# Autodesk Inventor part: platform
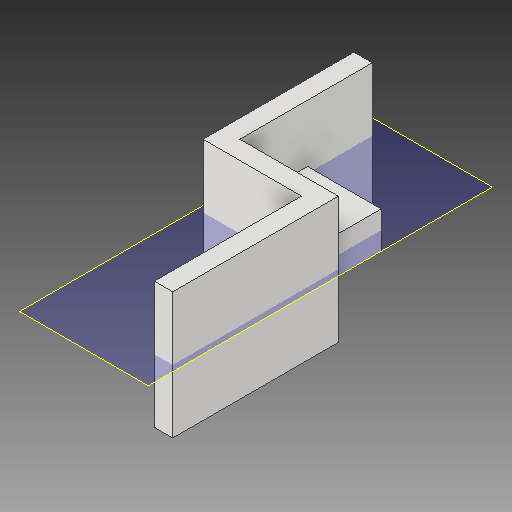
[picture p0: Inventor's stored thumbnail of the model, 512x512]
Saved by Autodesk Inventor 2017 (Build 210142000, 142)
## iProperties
Created: 2017-04
Part Number: platform
Material: LCP Plastic
Document SubType Name: Modeling
Designer: 1460374
Density: 1.626 g/cm^3
Appearance: Smooth - White
Author: 1460374
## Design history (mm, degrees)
sketch "Sketch1"
  geometry: L1 (-324.026, 5.525)-(-324.026, 11.875) reference; L2 (-332.942, 11.875)-(-324.026, 5.525) reference; L3 (-332.942, 11.875)-(-315.942, 11.875); L4 (-315.942, 11.875)-(-315.942, -9.969); L5 (-315.942, -9.969)-(-332.942, -9.969); L6 (-332.942, -9.969)-(-332.942, 11.875); 1 further point
  constraints: 8 end point, 2 parallel, 1 horizontal, 1 perpendicular
  dimensions: "d0" = 17 distance of L4.end L5.end; "d1" = 21.844 distance of L3.end L4.end
extrude "Extrusion1" new body sketch "Sketch1" distance "d2" = 3.175; taper "d3" = 0 deg
sketch "Sketch2"
  geometry: L1 (332.942, 11.875)-(332.942, -9.969) reference; L2 (315.942, 11.875)-(332.942, 11.875) reference; L3 (332.942, -9.969)-(329.767, -9.969); L4 (329.767, -9.969)-(329.767, 11.875); L5 (329.767, 11.875)-(332.942, 11.875); L6 (332.942, 11.875)-(332.942, -9.969); 1 further point
  constraints: 8 end point, 2 parallel, 1 horizontal, 1 perpendicular, 1 point on line
  dimensions: "d4" = 3.175 distance of L4.end L5.end
extrude "Extrusion2" join sketch "Sketch2" distance "d5" = 22.86; taper "d6" = 0 deg
sketch "Sketch3"
  geometry: L1 (0, 0)-(-28.575, 0); L2 (-28.575, 0)-(-28.575, 21.844); L3 (-28.575, 21.844)-(0, 21.844); L4 (0, 21.844)-(0, 0); 1 further point
  constraints: 8 end point, 2 parallel, 1 horizontal, 1 perpendicular
  dimensions: "d7" = 28.575 distance of L2.end L3.end
extrude "Extrusion3" join sketch "Sketch3" distance "d8" = 3.175; taper "d9" = 0 deg
workplane "Work Plane1"
workplane "Work Plane2"
sketch "Sketch5"
  geometry: L1 (20.175, 22.86)-(3.175, 22.86) reference; L2 (3.175, 22.86)-(3.175, 0) reference; L3 (5.325, 22.86)-(5.325, 13.335); L4 (5.325, 13.335)-(18.025, 13.335); L5 (18.025, 13.335)-(18.025, 22.86); L6 (3.175, 22.86)-(20.175, 22.86) reference; L7 (18.025, 32.385)-(5.325, 13.335); L8 (5.325, 32.385)-(18.025, 13.335); 2 further points
  constraints: 10 end point, 3 midpoint, 2 point on line, 1 parallel
  dimensions: "d14" = 12.7 distance of L4.end L3.end
extrude "Extrusion5" join sketch "Sketch5" stored distance "d15" = 6.35; taper "d16" = 0 deg
workplane "Work Plane6"
sketch "Sketch6"
  geometry: L1 (5.325, 22.86)-(18.025, 13.335); C1 r 1.905 at (11.675, 18.098); 1 further point
  constraints: 2 end point, 1 centre point, 1 midpoint
  dimensions: "d24" = 3.81 diameter of C1
extrude "Extrusion6" join sketch "Sketch6" stored distance "d17" = 6.35; taper "d18" = 0 deg
sketch "Sketch13"
  geometry: C1 r 1.905 at (11.675, 18.098) reference; C2 r 4.001 at (11.675, 18.098); 1 further point
  constraints: 1 centre point, 1 coincident
  dimensions: "d28" = 8.001 diameter of C2
extrude "Extrusion9" join sketch "Sketch13" distance "d29" = 1.9558; taper "d30" = 0 deg
body "Solid1"
node "Reference1"
node "Reference2"
node "Reference3"
node "Reference4"
node "Reference5"
node "Reference6"
